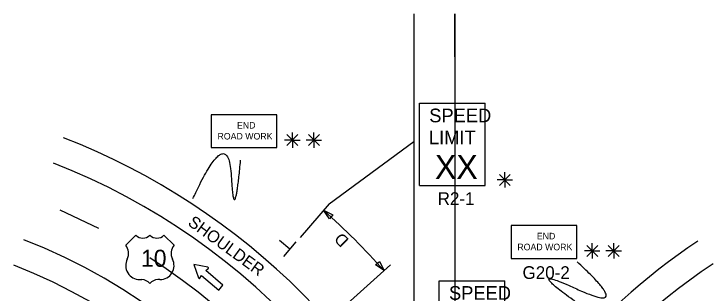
# Model space of a CAD drawing. Extents: x 16303 to 18479, y 5704 to 6974.
# Drawn here: x 16746.9 to 17155.7, y 6811 to 6974.1 of the extents above; entities that cross this region are included whole.
import ezdxf

# ---------------------------------------------------------------- set-up
doc = ezdxf.new("R2010")
doc.units = 0
for name, color, linetype in [('ALI_LEGAL_EX', 7, 'Continuous'), ('MT_SCRATCH_LEVEL_E', 7, 'Continuous'), ('PAVT_EDGE_EX', 7, 'Continuous'), ('TRAFFIC_SIGNS_PR', 7, 'Continuous'), ('TYPICAL_EX', 7, 'Continuous'), ('TYPICAL_TEXT_DIMEN_PR', 7, 'Continuous')]:
    doc.layers.add(name, color=color, linetype=linetype)

msp = doc.modelspace()

# ---------------------------------------------------------------- linework, layer by layer
at = {"layer": 'ALI_LEGAL_EX'}
for p, q in [((16980.68, 6974.12), (16980.68, 6155.98)), ((17004.68, 6974.12), (17004.68, 6155.98)), ((16980.68, 6877.04), (16980.68, 6013.12)), ((17004.68, 6877.04), (17004.68, 6013.12))]:
    msp.add_line(p, q, dxfattribs=at)
for points in [[(17004.68, 6949.12), (17004.68, 6974.12)], [(16796.64, 6848.72), (16773.99, 6859.31)]]:
    msp.add_lwpolyline(points, dxfattribs=at)
msp.add_arc((16629.65, 6525.15), 364, 0, 57.2958, dxfattribs=at)
at = {"layer": 'MT_SCRATCH_LEVEL_E'}
for p, q in [((16860.24, 6826.04), (16852.05, 6827.62)), ((16852.05, 6827.62), (16854.86, 6819.78)), ((16859.05, 6824.09), (16860.45, 6825.23)), ((16869.1, 6815.45), (16859.05, 6824.09)), ((16855.69, 6819.7), (16856.61, 6821.26)), ((16856.61, 6821.26), (16866.66, 6812.61)), ((16866.66, 6812.61), (16869.1, 6815.45))]:
    msp.add_line(p, q, dxfattribs=at)
for centre, start, end in [((16860.15, 6825.59), 309.3361, 79.073), ((16855.3, 6819.95), 199.7248, 329.2637)]:
    msp.add_arc(centre, 0.463, start, end, dxfattribs=at)
at = {"layer": 'PAVT_EDGE_EX'}
for centre, radius, start, end in [((16629.65, 6525.15), 404, 21.0961, 68.7791), ((16629.65, 6525.15), 388, 14.0482, 68.7791), ((16629.65, 6525.15), 340, 0, 68.7791), ((17357.65, 6525.15), 380, 123.6935, 157.5011), ((16629.65, 6525.15), 324, 0, 68.7791), ((17357.65, 6525.15), 364, 123.6935, 165.0045)]:
    msp.add_arc(centre, radius, start, end, dxfattribs=at)
at = {"layer": 'TRAFFIC_SIGNS_PR'}
for p, q in [((16983.99, 6921.9), (17022.39, 6921.9)), ((16983.99, 6873.9), (16983.99, 6921.9)), ((17022.39, 6873.9), (17022.39, 6921.9)), ((16983.99, 6873.9), (17022.39, 6873.9)), ((16995.55, 6818.12), (17033.95, 6818.12)), ((16995.55, 6770.12), (16995.55, 6818.12)), ((17033.95, 6770.12), (17033.95, 6818.12))]:
    msp.add_line(p, q, dxfattribs=at)
for points in [[(16862.33, 6895.99), (16900.73, 6895.99), (16900.73, 6915.19), (16862.33, 6915.19)], [(17037.68, 6831.2), (17076.08, 6831.2), (17076.08, 6850.4), (17037.68, 6850.4)]]:
    msp.add_lwpolyline(points, close=True, dxfattribs=at)
at = {"layer": 'TYPICAL_EX'}
for p, q in [((16812.25, 6838.84), (16818.14, 6844.74)), ((16840.55, 6838.84), (16834.65, 6844.74)), ((16820.49, 6818.78), (16821.67, 6818.78)), ((16832.3, 6818.78), (16831.12, 6818.78))]:
    msp.add_line(p, q, dxfattribs=at)
for centre, radius, start, end in [((16822.27, 6849.03), 5.96, 226.1404, 313.8596), ((16830.52, 6849.03), 5.96, 226.1404, 313.8596), ((16806.66, 6834.12), 7.31, 333.0977, 40.1936), ((16846.13, 6834.12), 7.31, 139.8064, 206.9023), ((16820.51, 6827.03), 8.24, 152.6698, 269.9013), ((16832.29, 6827.03), 8.24, 270.0987, 27.3302), ((16821.69, 6812.88), 5.91, 37.1038, 90.1385), ((16831.11, 6812.88), 5.91, 89.8615, 142.8962)]:
    msp.add_arc(centre, radius, start, end, dxfattribs=at)
at = {"layer": 'TYPICAL_TEXT_DIMEN_PR'}
for p, q in [((16909.75, 6900.36), (16909.75, 6904.82)), ((16922.31, 6900.36), (16922.31, 6904.82)), ((16912.94, 6903.55), (16906.56, 6897.17)), ((16906.57, 6903.55), (16912.94, 6897.17)), ((16919.12, 6903.55), (16925.5, 6897.17)), ((16925.5, 6903.55), (16919.12, 6897.17)), ((16909.75, 6900.36), (16905.22, 6900.36)), ((16909.75, 6900.36), (16912.94, 6900.36)), ((16909.75, 6900.36), (16914.23, 6900.36)), ((16909.75, 6900.36), (16909.75, 6895.86)), ((16922.31, 6900.36), (16917.78, 6900.36)), ((16922.31, 6900.36), (16925.5, 6900.36)), ((16922.31, 6900.36), (16926.79, 6900.36)), ((16922.31, 6900.36), (16922.31, 6895.86)), ((16931.32, 6863.17), (16980.76, 6899.6)), ((17030.79, 6880.28), (17037.17, 6873.9)), ((17037.17, 6880.28), (17030.79, 6873.9)), ((17033.98, 6877.09), (17033.98, 6881.55)), ((17033.98, 6877.09), (17029.44, 6877.09)), ((17033.98, 6877.09), (17037.17, 6877.09)), ((17033.98, 6877.09), (17038.46, 6877.09)), ((17033.98, 6877.09), (17033.98, 6872.59)), ((16931.32, 6863.17), (16914.34, 6843.48)), ((16931.42, 6854.32), (16928.01, 6859.34)), ((16928.01, 6859.34), (16933.48, 6856.7)), ((16932.45, 6855.51), (16931.42, 6854.32)), ((16933.48, 6856.7), (16932.45, 6855.51)), ((16908.16, 6836.56), (16902.26, 6841.65)), ((16911.83, 6840.82), (16904.48, 6832.31)), ((17085.1, 6835.57), (17085.1, 6840.03)), ((17097.66, 6835.57), (17097.66, 6840.03)), ((17085.1, 6835.57), (17080.57, 6835.57)), ((17081.92, 6838.76), (17088.29, 6832.38)), ((17088.29, 6838.76), (17081.92, 6832.38)), ((17085.1, 6835.57), (17088.29, 6835.57)), ((17085.1, 6835.57), (17089.58, 6835.57)), ((17085.1, 6835.57), (17085.1, 6831.07)), ((17097.66, 6835.57), (17093.13, 6835.57)), ((17094.47, 6838.76), (17100.85, 6832.38)), ((17100.85, 6838.76), (17094.47, 6832.38)), ((17097.66, 6835.57), (17100.85, 6835.57)), ((17097.66, 6835.57), (17102.14, 6835.57)), ((17097.66, 6835.57), (17097.66, 6831.07)), ((16967.1, 6827.36), (16923.44, 6788.26)), ((16958.3, 6827.35), (16959.47, 6828.39)), ((16963.38, 6824.03), (16958.3, 6827.35)), ((16959.47, 6828.39), (16960.64, 6829.44)), ((16960.64, 6829.44), (16963.38, 6824.03))]:
    msp.add_line(p, q, dxfattribs=at)
msp.add_arc((16629.65, 6525.15), 448, 41.8471, 48.2417, dxfattribs=at)
for points in [[(16851.6, 6866.22), (16872.23, 6911.03), (16875.68, 6847.69), (16879.45, 6888.56)], [(17086.35, 6798.24), (17039.53, 6830.07), (17110.85, 6797.33), (17076.24, 6829.21)]]:
    msp.add_open_spline(points, degree=2, dxfattribs=at)

# ---------------------------------------------------------------- texts
at = {"layer": 'TRAFFIC_SIGNS_PR'}
for s, height, p in [('SPEED', 8, (16989.76, 6910.77)), ('END', 3.831, (16877.33, 6907.12)), ('ROAD WORK', 3.831, (16865.94, 6900.73)), ('LIMIT', 8, (16989.59, 6897.97)), ('XX', 14.031, (16993.1, 6877.66)), ('R2-1', 7.44, (16994.67, 6862.46)), ('END', 3.831, (17052.68, 6842.32)), ('ROAD WORK', 3.831, (17041.29, 6835.94)), ('G20-2', 7.44, (17044.31, 6819.18)), ('SPEED', 8, (17001.31, 6806.98))]:
    msp.add_text(s, height=height, dxfattribs=at).set_placement(p)
at = {"layer": 'TYPICAL_EX'}
msp.add_text('10', height=10, dxfattribs=at).set_placement((16821.24, 6826.27))
at = {"layer": 'TYPICAL_TEXT_DIMEN_PR'}
for s, rotation, p in [('SHOULDER', 323.9582, (16848.09, 6851.02)), ('D', 135.5356, (16943.28, 6842.1))]:
    msp.add_text(s, height=7, rotation=rotation, dxfattribs=at).set_placement(p)

doc.saveas('drawing.dxf')
